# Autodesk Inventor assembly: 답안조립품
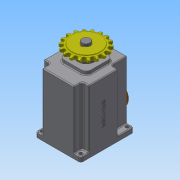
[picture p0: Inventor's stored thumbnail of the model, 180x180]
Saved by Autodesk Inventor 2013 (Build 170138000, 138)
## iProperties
Created: 2017-12
Part Number: 답안조립품
Document SubType Name: Assembly
Designer: Administrator
Author: Administrator
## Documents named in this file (17)
- C:\Users\Administrator\Desktop\371208V1021\답안조립품.iam
- C:\Users\Administrator\Desktop\371208V1021\가변스프링.ipt
- C:\Users\Administrator\Desktop\371208V1021\멈춤나사 M3x8.ipt
- C:\Users\Administrator\Desktop\371208V1021\메인축.ipt
- C:\Users\Administrator\Desktop\371208V1021\베어링 608.ipt
- C:\Users\Administrator\Desktop\371208V1021\베어링 6003.ipt
- C:\Users\Administrator\Desktop\371208V1021\본체.ipt
- C:\Users\Administrator\Desktop\371208V1021\볼트 M4 x 10.ipt
- C:\Users\Administrator\Desktop\371208V1021\부시.ipt
- C:\Users\Administrator\Desktop\371208V1021\상부 캡.ipt
- C:\Users\Administrator\Desktop\371208V1021\서브축.ipt
- C:\Users\Administrator\Desktop\371208V1021\스프로킷.ipt
- C:\Users\Administrator\Desktop\371208V1021\슬라이더.ipt
- C:\Users\Administrator\Desktop\371208V1021\오일 실 8 22 7.ipt
- C:\Users\Administrator\Desktop\371208V1021\오일 실 17 32 8.ipt
- C:\Users\Administrator\Desktop\371208V1021\커버.ipt
- C:\Users\Administrator\Desktop\371208V1021\키 5 x 5 x 18.ipt
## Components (1 placed, 1 different names)
1. 가변스프링:1
